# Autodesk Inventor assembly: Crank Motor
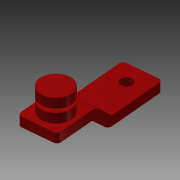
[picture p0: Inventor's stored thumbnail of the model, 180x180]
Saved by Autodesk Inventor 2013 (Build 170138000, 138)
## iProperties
Created: 2006-03
Part Number: Crank Motor
Document SubType Name: Assembly
Designer: Autodesk, Inc.
Mass: 66.6537 g
Surface Area: 48.811 cm^2
Volume: 8.60048 cm^3
Density: 7.75 g/cm^3
Author: Autodesk, Inc.
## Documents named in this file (3)
- C:\Users\boganb\Documents\B2 Design\Goodyear\2013 Tutorial Files\Dynamic Simulation 4\Components\Crank Motor.iam
- C:\Users\boganb\Documents\B2 Design\Goodyear\2013 Tutorial Files\Dynamic Simulation 4\Components\Crank_motor.ipt
- C:\Users\boganb\Documents\B2 Design\Goodyear\2013 Tutorial Files\Dynamic Simulation 4\Components\Pawn.ipt
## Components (2 placed, 2 different names)
1. Crank_motor:1 — Mate:1, Mate:2
2. Pawn:1 — Mate:1, Mate:2
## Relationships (2: Mate 2)
- Mate:1: Crank_motor:1 ↔ Pawn:1
- Mate:2: Crank_motor:1 ↔ Pawn:1
